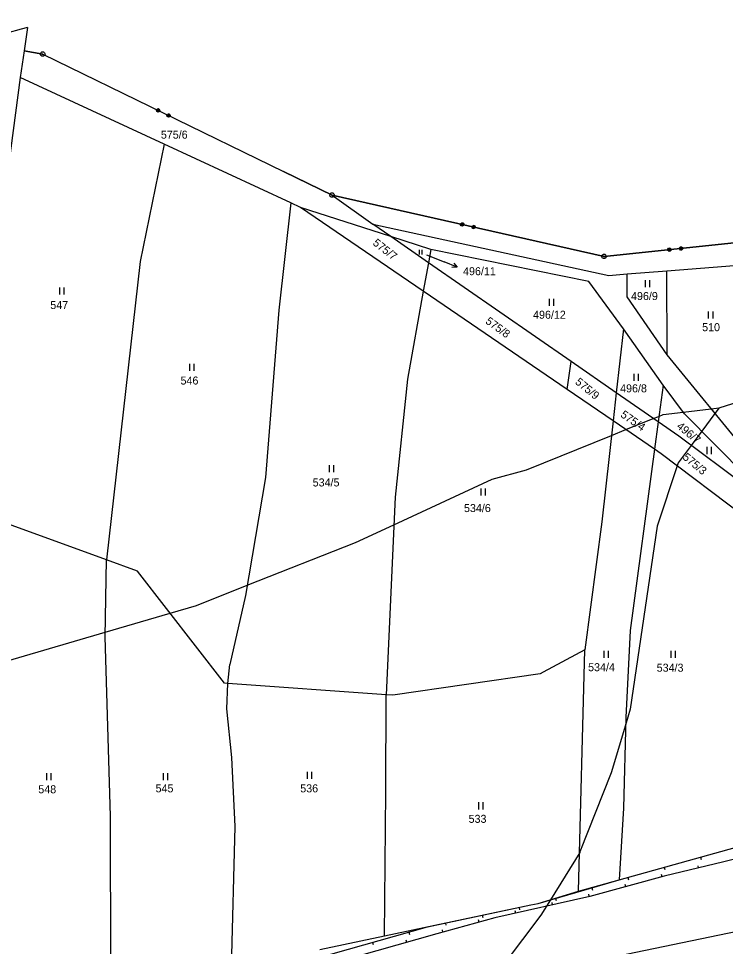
# Model space of a CAD drawing. Extents: x -760978 to -760029, y -1177282 to -1176414.
# Drawn here: x -760612.3 to -760462.2, y -1176625.4 to -1176428.3 of the extents above; entities that cross this region are included whole.
import ezdxf

# ---------------------------------------------------------------- set-up
doc = ezdxf.new("R2010")
doc.units = 0
for name, color, linetype in [('1', 7, 'Continuous'), ('11', 7, 'Continuous'), ('13', 7, 'Continuous'), ('2', 7, 'Continuous'), ('3', 7, 'Continuous'), ('7', 7, 'Continuous'), ('8', 7, 'Continuous')]:
    doc.layers.add(name, color=color, linetype=linetype)

msp = doc.modelspace()

# ---------------------------------------------------------------- linework, layer by layer
at = {"layer": '1'}
for p, q in [((-760611.11, -1176435.21), (-760611.97, -1176440.89)), ((-760607.21, -1176435.9), (-760611.11, -1176435.21)), ((-760607.21, -1176435.9), (-760556.03, -1176460.82)), ((-760611.97, -1176440.89), (-760617.06, -1176478.94)), ((-760581.4, -1176455.04), (-760611.97, -1176440.89)), ((-760581.4, -1176455.04), (-760586.47, -1176479.9)), ((-760554.5, -1176467.49), (-760581.4, -1176455.04)), ((-760545.74, -1176465.83), (-760556.03, -1176460.82)), ((-760554.5, -1176467.49), (-760557.05, -1176490.29)), ((-760552.45, -1176468.44), (-760554.5, -1176467.49)), ((-760487.96, -1176478.86), (-760545.74, -1176465.83)), ((-760545.74, -1176465.83), (-760537.11, -1176471.99)), ((-760533.27, -1176474.65), (-760552.45, -1176468.44)), ((-760526.36, -1176486.25), (-760552.45, -1176468.44)), ((-760533.27, -1176474.65), (-760537.11, -1176471.99)), ((-760537.11, -1176471.99), (-760486.95, -1176482.88)), ((-760524.78, -1176477.4), (-760533.27, -1176474.65)), ((-760525.28, -1176480.19), (-760533.27, -1176474.65)), ((-760524.78, -1176477.4), (-760525.28, -1176480.19)), ((-760491.22, -1176484.15), (-760524.78, -1176477.4)), ((-760457.63, -1176475.7), (-760487.96, -1176478.86)), ((-760586.47, -1176479.9), (-760593.68, -1176543.24)), ((-760525.28, -1176480.19), (-760526.36, -1176486.25)), ((-760494.97, -1176501.19), (-760525.28, -1176480.19)), ((-760474.63, -1176481.92), (-760455.21, -1176480.4)), ((-760486.95, -1176482.88), (-760483.06, -1176482.58)), ((-760483.09, -1176487.45), (-760483.06, -1176482.58)), ((-760483.06, -1176482.58), (-760474.63, -1176481.92)), ((-760474.58, -1176499.77), (-760474.63, -1176481.92)), ((-760483.84, -1176494.23), (-760491.22, -1176484.15)), ((-760526.36, -1176486.25), (-760529.7, -1176504.94)), ((-760495.84, -1176507.09), (-760526.36, -1176486.25)), ((-760474.58, -1176499.77), (-760483.09, -1176487.45)), ((-760557.05, -1176490.29), (-760559.9, -1176525.81)), ((-760483.84, -1176494.23), (-760485.37, -1176507.84)), ((-760475.45, -1176506.17), (-760483.84, -1176494.23)), ((-760495.84, -1176507.09), (-760494.97, -1176501.19)), ((-760485.37, -1176507.84), (-760494.97, -1176501.19)), ((-760457.19, -1176521.02), (-760474.58, -1176499.77)), ((-760529.7, -1176504.94), (-760532.32, -1176529.96)), ((-760486.04, -1176513.78), (-760495.84, -1176507.09)), ((-760475.45, -1176506.17), (-760476.5, -1176513.99)), ((-760470.91, -1176512.26), (-760475.45, -1176506.17)), ((-760485.37, -1176507.84), (-760486.04, -1176513.78)), ((-760476.5, -1176513.99), (-760485.37, -1176507.84)), ((-760457.78, -1176525.5), (-760470.91, -1176512.26)), ((-760486.04, -1176513.78), (-760488.45, -1176535.19)), ((-760477.28, -1176519.76), (-760486.04, -1176513.78)), ((-760476.5, -1176513.99), (-760477.28, -1176519.76)), ((-760472.1, -1176517.04), (-760476.5, -1176513.99)), ((-760457.89, -1176527.65), (-760472.1, -1176517.04)), ((-760477.28, -1176519.76), (-760482.45, -1176558.25)), ((-760475.84, -1176520.74), (-760477.28, -1176519.76)), ((-760458.21, -1176534.1), (-760475.84, -1176520.74)), ((-760559.9, -1176525.81), (-760564.13, -1176550.84)), ((-760532.32, -1176529.96), (-760534.23, -1176571.92)), ((-760593.68, -1176543.24), (-760617.76, -1176534.49)), ((-760488.45, -1176535.19), (-760492.03, -1176562.38)), ((-760593.96, -1176559.61), (-760593.68, -1176543.24)), ((-760587.04, -1176545.66), (-760593.68, -1176543.24)), ((-760568.58, -1176569.45), (-760587.04, -1176545.66)), ((-760564.13, -1176550.84), (-760567.47, -1176565.5)), ((-760482.45, -1176558.25), (-760483.37, -1176576.78)), ((-760592.8, -1176597.68), (-760593.96, -1176559.61)), ((-760492.03, -1176562.38), (-760500.9, -1176567.15)), ((-760493.37, -1176613.65), (-760492.03, -1176562.38)), ((-760567.86, -1176569.5), (-760567.47, -1176565.5)), ((-760501.57, -1176567.51), (-760532.81, -1176572.02)), ((-760500.9, -1176567.15), (-760501.57, -1176567.51)), ((-760567.86, -1176569.5), (-760568.58, -1176569.45)), ((-760568.12, -1176574.94), (-760567.86, -1176569.5)), ((-760534.23, -1176571.92), (-760567.86, -1176569.5)), ((-760534.34, -1176592.53), (-760534.23, -1176571.92)), ((-760532.81, -1176572.02), (-760534.23, -1176571.92)), ((-760567.04, -1176585.26), (-760568.12, -1176574.94)), ((-760483.37, -1176576.78), (-760483.84, -1176596.02)), ((-760566.35, -1176599.89), (-760567.04, -1176585.26)), ((-760534.62, -1176623.13), (-760534.34, -1176592.53)), ((-760592.73, -1176637.28), (-760592.8, -1176597.68)), ((-760483.84, -1176596.02), (-760484.78, -1176611.25)), ((-760567.14, -1176630.22), (-760566.35, -1176599.89)), ((-760484.78, -1176611.25), (-760460.12, -1176604.35)), ((-760493.37, -1176613.65), (-760484.78, -1176611.25)), ((-760501.99, -1176616.24), (-760493.37, -1176613.65)), ((-760534.62, -1176623.13), (-760503.5, -1176616.56)), ((-760503.5, -1176616.56), (-760501.99, -1176616.24)), ((-760452.06, -1176620.62), (-760503.19, -1176631.16)), ((-760548.37, -1176626.03), (-760534.62, -1176623.13))]:
    msp.add_line(p, q, dxfattribs=at)
for points in [[(-760582.44, -1176447.6), (-760582.35, -1176447.86), (-760582.47, -1176448.1), (-760582.73, -1176448.19), (-760582.97, -1176448.07), (-760583.06, -1176447.82), (-760582.94, -1176447.57), (-760582.68, -1176447.49), (-760582.44, -1176447.6), (-760582.47, -1176447.64), (-760582.68, -1176447.53), (-760582.79, -1176447.57), (-760582.43, -1176447.74), (-760582.39, -1176447.85), (-760582.9, -1176447.6), (-760582.93, -1176447.68), (-760582.43, -1176447.92), (-760582.46, -1176447.99), (-760582.97, -1176447.75), (-760583, -1176447.82), (-760582.5, -1176448.07), (-760582.61, -1176448.1), (-760582.97, -1176447.93), (-760582.93, -1176448.03), (-760582.71, -1176448.14)], [(-760580.19, -1176448.7), (-760580.11, -1176448.95), (-760580.22, -1176449.2), (-760580.48, -1176449.28), (-760580.72, -1176449.16), (-760580.81, -1176448.91), (-760580.69, -1176448.67), (-760580.44, -1176448.58), (-760580.19, -1176448.7), (-760580.24, -1176448.72), (-760580.45, -1176448.62), (-760580.56, -1176448.65), (-760580.2, -1176448.83), (-760580.16, -1176448.94), (-760580.67, -1176448.69), (-760580.7, -1176448.76), (-760580.2, -1176449.01), (-760580.23, -1176449.08), (-760580.74, -1176448.83), (-760580.77, -1176448.91), (-760580.27, -1176449.15), (-760580.38, -1176449.19), (-760580.74, -1176449.01), (-760580.7, -1176449.12), (-760580.48, -1176449.22)], [(-760518.32, -1176472.34), (-760518.46, -1176472.12), (-760518.4, -1176471.85), (-760518.17, -1176471.71), (-760517.91, -1176471.77), (-760517.77, -1176472), (-760517.82, -1176472.26), (-760518.05, -1176472.4), (-760518.32, -1176472.34), (-760518.28, -1176472.31), (-760518.04, -1176472.36), (-760517.95, -1176472.3), (-760518.34, -1176472.21), (-760518.4, -1176472.12), (-760517.85, -1176472.24), (-760517.83, -1176472.16), (-760518.38, -1176472.04), (-760518.36, -1176471.96), (-760517.82, -1176472.09), (-760517.8, -1176472.01), (-760518.35, -1176471.89), (-760518.25, -1176471.82), (-760517.86, -1176471.91), (-760517.92, -1176471.82), (-760518.15, -1176471.76)], [(-760515.88, -1176472.89), (-760516.02, -1176472.67), (-760515.96, -1176472.4), (-760515.73, -1176472.26), (-760515.47, -1176472.32), (-760515.33, -1176472.54), (-760515.39, -1176472.81), (-760515.61, -1176472.95), (-760515.88, -1176472.89), (-760515.86, -1176472.86), (-760515.62, -1176472.91), (-760515.53, -1176472.85), (-760515.92, -1176472.76), (-760515.98, -1176472.66), (-760515.43, -1176472.79), (-760515.41, -1176472.71), (-760515.96, -1176472.59), (-760515.94, -1176472.51), (-760515.4, -1176472.63), (-760515.38, -1176472.55), (-760515.93, -1176472.43), (-760515.83, -1176472.37), (-760515.44, -1176472.46), (-760515.5, -1176472.36), (-760515.73, -1176472.31)], [(-760474.18, -1176477.75), (-760474.39, -1176477.58), (-760474.42, -1176477.31), (-760474.25, -1176477.1), (-760473.98, -1176477.07), (-760473.77, -1176477.24), (-760473.75, -1176477.51), (-760473.92, -1176477.72), (-760474.18, -1176477.75), (-760474.16, -1176477.7), (-760473.92, -1176477.68), (-760473.85, -1176477.59), (-760474.25, -1176477.63), (-760474.33, -1176477.56), (-760473.78, -1176477.5), (-760473.79, -1176477.42), (-760474.34, -1176477.48), (-760474.35, -1176477.4), (-760473.79, -1176477.34), (-760473.8, -1176477.26), (-760474.36, -1176477.32), (-760474.29, -1176477.23), (-760473.89, -1176477.19), (-760473.98, -1176477.12), (-760474.22, -1176477.15)], [(-760471.7, -1176477.49), (-760471.91, -1176477.32), (-760471.93, -1176477.05), (-760471.76, -1176476.84), (-760471.5, -1176476.81), (-760471.29, -1176476.98), (-760471.26, -1176477.25), (-760471.43, -1176477.46), (-760471.7, -1176477.49), (-760471.69, -1176477.45), (-760471.45, -1176477.42), (-760471.38, -1176477.33), (-760471.78, -1176477.38), (-760471.87, -1176477.3), (-760471.31, -1176477.25), (-760471.32, -1176477.17), (-760471.88, -1176477.22), (-760471.88, -1176477.15), (-760471.33, -1176477.09), (-760471.34, -1176477.01), (-760471.89, -1176477.07), (-760471.82, -1176476.98), (-760471.42, -1176476.94), (-760471.51, -1176476.87), (-760471.75, -1176476.89)]]:
    msp.add_lwpolyline(points, dxfattribs=at)
at = {"layer": '11'}
for points in [[(-760610.45, -1176430.21), (-760611.11, -1176435.21), (-760607.21, -1176435.9), (-760556.03, -1176460.82), (-760555.89, -1176460.89), (-760545.74, -1176465.83), (-760487.96, -1176478.86), (-760457.63, -1176475.7), (-760439.57, -1176472.8), (-760424.85, -1176466.78), (-760424.82, -1176466.77), (-760413.52, -1176462.15), (-760377.01, -1176441.98), (-760344.63, -1176429.59), (-760316.13, -1176428.34), (-760276.6, -1176437.03), (-760267.18, -1176439.56), (-760261.76, -1176441.01)], [(-760610.45, -1176430.21), (-760611.76, -1176430.57), (-760614.8, -1176431.42), (-760614.95, -1176431.46)], [(-760463.52, -1176510.97), (-760456.38, -1176508.74), (-760455.84, -1176508.57), (-760440.39, -1176497.85), (-760434.43, -1176496.69), (-760400.64, -1176484.31), (-760369.55, -1176472.91), (-760361.85, -1176469.24), (-760336.22, -1176462.2), (-760324.34, -1176458.93), (-760306.03, -1176455.04), (-760299.86, -1176454.5), (-760269.91, -1176451.9), (-760264.83, -1176452.17), (-760257.19, -1176452.57), (-760239.84, -1176455.43), (-760233.95, -1176457.19), (-760221.69, -1176460.86), (-760206.87, -1176462.83), (-760202.63, -1176462.91), (-760198.26, -1176462.31), (-760192.1, -1176461.47), (-760183.97, -1176460.36)], [(-760618.86, -1176565.92), (-760593.94, -1176558.62), (-760580.12, -1176554.58), (-760574.54, -1176552.94), (-760563.77, -1176548.68), (-760540.79, -1176539.6), (-760532.59, -1176535.81), (-760511.72, -1176526.16), (-760504.47, -1176524.18), (-760486.39, -1176516.87), (-760483.32, -1176515.63), (-760477.51, -1176513.29), (-760476.34, -1176512.81), (-760475.43, -1176512.44), (-760471.17, -1176511.92), (-760465.24, -1176511.18), (-760463.52, -1176510.97)], [(-760463.52, -1176510.97), (-760464.42, -1176512.18), (-760467.23, -1176515.97), (-760469.48, -1176519), (-760472.2, -1176522.67), (-760472.42, -1176523.33), (-760476.67, -1176536.14), (-760482.4, -1176575), (-760483.41, -1176578.36), (-760486.44, -1176588.48), (-760493.09, -1176605.3), (-760493.15, -1176605.41), (-760499.36, -1176615.45), (-760501.37, -1176618.7)], [(-760501.37, -1176618.7), (-760513.07, -1176634.24), (-760513.95, -1176635.41), (-760524.86, -1176653.84), (-760528.45, -1176665.64), (-760528.48, -1176665.84), (-760530.61, -1176682.15), (-760530.88, -1176684.23), (-760527.99, -1176714.86), (-760526.55, -1176730.06), (-760525.81, -1176736.83), (-760523.24, -1176760.62), (-760521.34, -1176774.21)]]:
    msp.add_lwpolyline(points, dxfattribs=at)
at = {"layer": '13'}
for p, q in [((-760467.48, -1176606.41), (-760467.35, -1176606.89)), ((-760475.19, -1176608.57), (-760475.05, -1176609.05)), ((-760467.89, -1176608.7), (-760468.01, -1176608.22)), ((-760482.89, -1176610.72), (-760482.76, -1176611.2)), ((-760475.66, -1176610.6), (-760475.79, -1176610.12)), ((-760490.58, -1176612.93), (-760490.44, -1176613.41)), ((-760483.38, -1176612.7), (-760483.51, -1176612.21)), ((-760498.26, -1176615.16), (-760498.13, -1176615.64)), ((-760491.1, -1176614.79), (-760491.21, -1176614.3)), ((-760506.02, -1176617.09), (-760505.92, -1176617.58)), ((-760498.91, -1176616.54), (-760499.02, -1176616.05)), ((-760513.85, -1176618.74), (-760513.75, -1176619.23)), ((-760506.71, -1176618.3), (-760506.82, -1176617.81)), ((-760521.68, -1176620.39), (-760521.57, -1176620.88)), ((-760514.48, -1176620.21), (-760514.61, -1176619.73)), ((-760529.44, -1176622.32), (-760529.3, -1176622.8)), ((-760522.19, -1176622.34), (-760522.32, -1176621.86)), ((-760537.14, -1176624.49), (-760537, -1176624.98)), ((-760529.89, -1176624.51), (-760530.02, -1176624.03))]:
    msp.add_line(p, q, dxfattribs=at)
for points in [[(-760433.58, -1176600.16), (-760462.53, -1176607.4), (-760475.17, -1176610.47), (-760490.99, -1176614.76), (-760511.18, -1176619.3), (-760523.48, -1176622.7), (-760548.95, -1176629.91)], [(-760549.29, -1176627.93), (-760525.45, -1176621.19), (-760503.5, -1176616.56), (-760501.99, -1176616.24), (-760484.78, -1176611.25), (-760460.12, -1176604.35)]]:
    msp.add_lwpolyline(points, dxfattribs=at)
at = {"layer": '3'}
for p, q in [((-760527.27, -1176477.44), (-760527.27, -1176478.45)), ((-760526.6, -1176478.45), (-760526.6, -1176477.44)), ((-760603.67, -1176485.44), (-760603.67, -1176486.94)), ((-760602.67, -1176486.94), (-760602.67, -1176485.44)), ((-760479.25, -1176483.88), (-760479.25, -1176485.38)), ((-760478.25, -1176485.38), (-760478.25, -1176483.88)), ((-760499.63, -1176487.86), (-760499.63, -1176489.36)), ((-760498.63, -1176489.36), (-760498.63, -1176487.86)), ((-760465.83, -1176490.56), (-760465.83, -1176492.06)), ((-760464.83, -1176492.06), (-760464.83, -1176490.56)), ((-760576.06, -1176501.65), (-760576.06, -1176503.15)), ((-760575.06, -1176503.15), (-760575.06, -1176501.65)), ((-760481.68, -1176503.75), (-760481.68, -1176505.25)), ((-760480.68, -1176505.25), (-760480.68, -1176503.75)), ((-760466.12, -1176519.31), (-760466.12, -1176520.81)), ((-760465.12, -1176520.81), (-760465.12, -1176519.31)), ((-760546.37, -1176523.19), (-760546.37, -1176524.69)), ((-760545.37, -1176524.69), (-760545.37, -1176523.19)), ((-760514.15, -1176528.1), (-760514.15, -1176529.6)), ((-760513.15, -1176529.6), (-760513.15, -1176528.1)), ((-760488.03, -1176562.57), (-760488.03, -1176564.07)), ((-760487.03, -1176564.07), (-760487.03, -1176562.57)), ((-760473.77, -1176562.57), (-760473.77, -1176564.07)), ((-760472.77, -1176564.07), (-760472.77, -1176562.57)), ((-760606.4, -1176588.55), (-760606.4, -1176590.05)), ((-760605.4, -1176590.05), (-760605.4, -1176588.55)), ((-760581.63, -1176588.55), (-760581.63, -1176590.05)), ((-760580.63, -1176590.05), (-760580.63, -1176588.55)), ((-760551.04, -1176588.29), (-760551.04, -1176589.79)), ((-760550.04, -1176589.79), (-760550.04, -1176588.29)), ((-760514.67, -1176594.76), (-760514.67, -1176596.26)), ((-760513.67, -1176596.26), (-760513.67, -1176594.76))]:
    msp.add_line(p, q, dxfattribs=at)
at = {"layer": '7'}
for p in [(-760525.71, -1176478.48), (-760519.16, -1176481.14)]:
    msp.add_line(p, (-760521.94, -1176480.01), dxfattribs=at)
msp.add_lwpolyline([(-760519.9, -1176480.3), (-760519.16, -1176481.14), (-760520.27, -1176481.23)], dxfattribs=at)
at = {"layer": '8'}
for p, q in [((-760607.33, -1176435.9), (-760607.09, -1176435.9)), ((-760545.86, -1176465.83), (-760545.62, -1176465.83)), ((-760488.08, -1176478.86), (-760487.84, -1176478.86))]:
    msp.add_line(p, q, dxfattribs=at)
for points in [[(-760607.06, -1176435.42), (-760606.81, -1176435.6), (-760606.71, -1176435.89), (-760606.81, -1176436.18), (-760607.06, -1176436.36), (-760607.37, -1176436.36), (-760607.62, -1176436.18), (-760607.72, -1176435.89), (-760607.62, -1176435.6), (-760607.37, -1176435.42)], [(-760545.59, -1176465.35), (-760545.34, -1176465.53), (-760545.24, -1176465.82), (-760545.34, -1176466.11), (-760545.59, -1176466.29), (-760545.9, -1176466.29), (-760546.15, -1176466.11), (-760546.25, -1176465.82), (-760546.15, -1176465.53), (-760545.9, -1176465.35)], [(-760487.81, -1176478.38), (-760487.56, -1176478.56), (-760487.46, -1176478.85), (-760487.56, -1176479.14), (-760487.81, -1176479.32), (-760488.12, -1176479.32), (-760488.37, -1176479.14), (-760488.47, -1176478.85), (-760488.37, -1176478.56), (-760488.12, -1176478.38)]]:
    msp.add_lwpolyline(points, close=True, dxfattribs=at)

# ---------------------------------------------------------------- texts
at = {"layer": '2'}
for s, height, p in [('575/6', 1.7, (-760582.11, -1176453.84)), ('496/11', 0.1, (-760525.91, -1176478.48)), ('496/9', 1.7, (-760482.24, -1176488.11)), ('547', 1.7, (-760605.59, -1176490.02)), ('496/12', 1.7, (-760503.05, -1176492.08)), ('510', 1.7, (-760467.14, -1176494.72)), ('546', 1.7, (-760577.93, -1176506.05)), ('496/8', 1.7, (-760484.56, -1176507.71)), ('534/5', 1.7, (-760549.86, -1176527.69)), ('534/6', 1.7, (-760517.72, -1176533.13)), ('534/4', 1.7, (-760491.36, -1176566.92)), ('534/3', 1.7, (-760476.79, -1176567.03)), ('548', 1.7, (-760608.14, -1176592.84)), ('545', 1.7, (-760583.23, -1176592.64)), ('536', 1.7, (-760552.5, -1176592.65)), ('533', 1.7, (-760516.74, -1176599.12))]:
    msp.add_text(s, height=height, dxfattribs=at).set_placement(p)
for s, rotation, p in [('575/7', 321.7158, (-760537.24, -1176476.26)), ('575/8', 323.893, (-760513.31, -1176492.93)), ('575/9', 320.5126, (-760494.24, -1176505.76)), ('575/4', 325.2108, (-760484.62, -1176512.8)), ('496/7', 320.398, (-760472.7, -1176515.15)), ('575/3', 320.3407, (-760471.42, -1176521.73))]:
    msp.add_text(s, height=1.7, rotation=rotation, dxfattribs=at).set_placement(p)
at = {"layer": '7'}
msp.add_text('496/11', height=1.7, dxfattribs=at).set_placement((-760517.92, -1176482.84))

doc.saveas('drawing.dxf')
